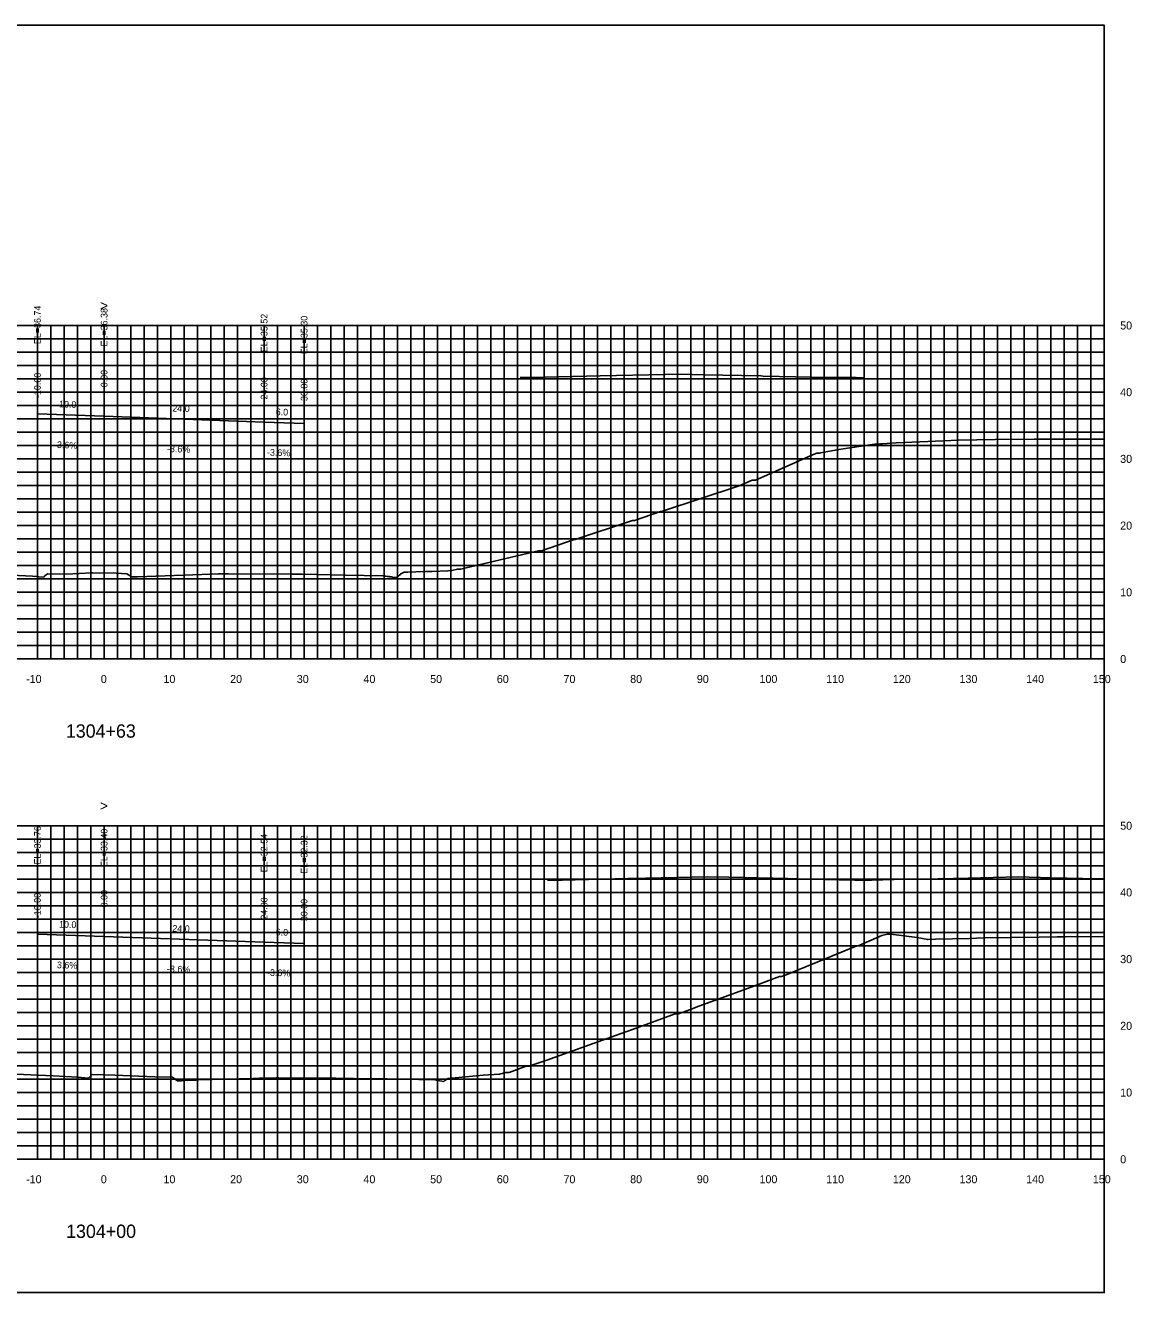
# Model space of a CAD drawing. Extents: x 1797714 to 1804825, y 249015 to 250269.
# Drawn here: x 1803612.3 to 1803778.3, y 249628.2 to 249818.2 of the extents above; entities that cross this region are included whole.
import ezdxf

# ---------------------------------------------------------------- set-up
doc = ezdxf.new("R2010")
doc.units = 0
for name, color, linetype in [('1', 7, 'Continuous'), ('10', 7, 'Continuous'), ('3', 7, 'Continuous'), ('31', 7, 'Continuous'), ('4', 7, 'Continuous'), ('60', 7, 'Continuous'), ('CL-CNST', 7, 'Continuous'), ('Level 62', 7, 'Continuous'), ('M-ROADS', 7, 'Continuous')]:
    doc.layers.add(name, color=color, linetype=linetype)

msp = doc.modelspace()

# ---------------------------------------------------------------- linework, layer by layer
for p, q in [((1803614.16, 249759.91), (1803614.16, 249761.91)), ((1803624.16, 249759.55), (1803624.16, 249761.55)), ((1803648.16, 249758.69), (1803648.16, 249760.69)), ((1803654.16, 249758.47), (1803654.16, 249760.47)), ((1803614.16, 249681.93), (1803614.16, 249683.93)), ((1803624.16, 249681.57), (1803624.16, 249683.57)), ((1803648.16, 249680.71), (1803648.16, 249682.71)), ((1803654.16, 249680.49), (1803654.16, 249682.49))]:
    msp.add_line(p, q)
msp.add_lwpolyline([(1803474.16, 249628.17), (1803774.16, 249628.17), (1803774.16, 249818.17), (1803474.16, 249818.17)], close=True)
at = {"layer": '60'}
for p, q in [((1803774.16, 249723.17), (1803774.16, 249773.17)), ((1803774.22, 249773.17), (1803774.16, 249773.17)), ((1803774.22, 249763.17), (1803774.16, 249763.17)), ((1803774.22, 249753.17), (1803774.16, 249753.17)), ((1803774.22, 249743.17), (1803774.16, 249743.17)), ((1803774.22, 249733.17), (1803774.16, 249733.17)), ((1803474.16, 249723.17), (1803774.16, 249723.17)), ((1803614.16, 249723.11), (1803614.16, 249723.17)), ((1803624.16, 249723.11), (1803624.16, 249723.17)), ((1803634.16, 249723.11), (1803634.16, 249723.17)), ((1803644.16, 249723.11), (1803644.16, 249723.17)), ((1803654.16, 249723.11), (1803654.16, 249723.17)), ((1803664.16, 249723.11), (1803664.16, 249723.17)), ((1803674.16, 249723.11), (1803674.16, 249723.17)), ((1803684.16, 249723.11), (1803684.16, 249723.17)), ((1803694.16, 249723.11), (1803694.16, 249723.17)), ((1803704.16, 249723.11), (1803704.16, 249723.17)), ((1803714.16, 249723.11), (1803714.16, 249723.17)), ((1803724.16, 249723.11), (1803724.16, 249723.17)), ((1803734.16, 249723.11), (1803734.16, 249723.17)), ((1803744.16, 249723.11), (1803744.16, 249723.17)), ((1803754.16, 249723.11), (1803754.16, 249723.17)), ((1803764.16, 249723.11), (1803764.16, 249723.17)), ((1803774.16, 249723.11), (1803774.16, 249723.17)), ((1803774.22, 249723.17), (1803774.16, 249723.17)), ((1803774.16, 249648.17), (1803774.16, 249698.17)), ((1803774.22, 249698.17), (1803774.16, 249698.17)), ((1803774.22, 249688.17), (1803774.16, 249688.17)), ((1803774.22, 249678.17), (1803774.16, 249678.17)), ((1803774.22, 249668.17), (1803774.16, 249668.17)), ((1803774.22, 249658.17), (1803774.16, 249658.17)), ((1803474.16, 249648.17), (1803774.16, 249648.17)), ((1803614.16, 249648.11), (1803614.16, 249648.17)), ((1803624.16, 249648.11), (1803624.16, 249648.17)), ((1803634.16, 249648.11), (1803634.16, 249648.17)), ((1803644.16, 249648.11), (1803644.16, 249648.17)), ((1803654.16, 249648.11), (1803654.16, 249648.17)), ((1803664.16, 249648.11), (1803664.16, 249648.17)), ((1803674.16, 249648.11), (1803674.16, 249648.17)), ((1803684.16, 249648.11), (1803684.16, 249648.17)), ((1803694.16, 249648.11), (1803694.16, 249648.17)), ((1803704.16, 249648.11), (1803704.16, 249648.17)), ((1803714.16, 249648.11), (1803714.16, 249648.17)), ((1803724.16, 249648.11), (1803724.16, 249648.17)), ((1803734.16, 249648.11), (1803734.16, 249648.17)), ((1803744.16, 249648.11), (1803744.16, 249648.17)), ((1803754.16, 249648.11), (1803754.16, 249648.17)), ((1803764.16, 249648.11), (1803764.16, 249648.17)), ((1803774.16, 249648.11), (1803774.16, 249648.17)), ((1803774.22, 249648.17), (1803774.16, 249648.17))]:
    msp.add_line(p, q, dxfattribs=at)
at = {"layer": 'CL-CNST'}
for points in [[(1803686.54, 249765.35), (1803688.22, 249765.39), (1803698.58, 249765.61), (1803708.3, 249765.82), (1803710.63, 249765.87), (1803714.11, 249765.79), (1803722.67, 249765.6), (1803723, 249765.59), (1803732.7, 249765.37), (1803732.79, 249765.37), (1803733.95, 249765.35), (1803733.95, 249765.35), (1803734.04, 249765.35), (1803734.82, 249765.36), (1803735.82, 249765.39), (1803736.94, 249765.37), (1803738.17, 249765.34)], [(1803614.16, 249759.91), (1803624.16, 249759.55), (1803648.16, 249758.69), (1803654.16, 249758.47)], [(1803690.67, 249689.99), (1803692.88, 249690.03), (1803702.69, 249690.25), (1803705.37, 249690.3), (1803714.71, 249690.51), (1803717.86, 249690.44), (1803726.72, 249690.24), (1803729.72, 249690.17), (1803736.74, 249690.02), (1803737.14, 249690.01), (1803737.98, 249689.99), (1803737.99, 249689.99), (1803737.99, 249689.99), (1803738.4, 249690), (1803739.24, 249690.01), (1803742.64, 249690.09), (1803749.25, 249690.23), (1803753.75, 249690.33), (1803761.27, 249690.49), (1803766.24, 249690.38), (1803773.29, 249690.22), (1803774.16, 249690.2)], [(1803614.16, 249681.93), (1803624.16, 249681.57), (1803648.16, 249680.71), (1803654.16, 249680.49)]]:
    msp.add_lwpolyline(points, dxfattribs=at)
at = {"layer": 'Level 62'}
for p, q in [((1803474.16, 249773.17), (1803774.16, 249773.17)), ((1803614.16, 249723.17), (1803614.16, 249773.17)), ((1803616.16, 249723.17), (1803616.16, 249773.17)), ((1803618.16, 249723.17), (1803618.16, 249773.17)), ((1803620.16, 249723.17), (1803620.16, 249773.17)), ((1803622.16, 249723.17), (1803622.16, 249773.17)), ((1803624.16, 249723.17), (1803624.16, 249773.17)), ((1803626.16, 249723.17), (1803626.16, 249773.17)), ((1803628.16, 249723.17), (1803628.16, 249773.17)), ((1803630.16, 249723.17), (1803630.16, 249773.17)), ((1803632.16, 249723.17), (1803632.16, 249773.17)), ((1803634.16, 249723.17), (1803634.16, 249773.17)), ((1803636.16, 249723.17), (1803636.16, 249773.17)), ((1803638.16, 249723.17), (1803638.16, 249773.17)), ((1803640.16, 249723.17), (1803640.16, 249773.17)), ((1803642.16, 249723.17), (1803642.16, 249773.17)), ((1803644.16, 249723.17), (1803644.16, 249773.17)), ((1803646.16, 249723.17), (1803646.16, 249773.17)), ((1803648.16, 249723.17), (1803648.16, 249773.17)), ((1803650.16, 249723.17), (1803650.16, 249773.17)), ((1803652.16, 249723.17), (1803652.16, 249773.17)), ((1803654.16, 249723.17), (1803654.16, 249773.17)), ((1803656.16, 249723.17), (1803656.16, 249773.17)), ((1803658.16, 249723.17), (1803658.16, 249773.17)), ((1803660.16, 249723.17), (1803660.16, 249773.17)), ((1803662.16, 249723.17), (1803662.16, 249773.17)), ((1803664.16, 249723.17), (1803664.16, 249773.17)), ((1803666.16, 249723.17), (1803666.16, 249773.17)), ((1803668.16, 249723.17), (1803668.16, 249773.17)), ((1803670.16, 249723.17), (1803670.16, 249773.17)), ((1803672.16, 249723.17), (1803672.16, 249773.17)), ((1803674.16, 249723.17), (1803674.16, 249773.17)), ((1803676.16, 249723.17), (1803676.16, 249773.17)), ((1803678.16, 249723.17), (1803678.16, 249773.17)), ((1803680.16, 249723.17), (1803680.16, 249773.17)), ((1803682.16, 249723.17), (1803682.16, 249773.17)), ((1803684.16, 249723.17), (1803684.16, 249773.17)), ((1803686.16, 249723.17), (1803686.16, 249773.17)), ((1803688.16, 249723.17), (1803688.16, 249773.17)), ((1803690.16, 249723.17), (1803690.16, 249773.17)), ((1803692.16, 249723.17), (1803692.16, 249773.17)), ((1803694.16, 249723.17), (1803694.16, 249773.17)), ((1803696.16, 249723.17), (1803696.16, 249773.17)), ((1803698.16, 249723.17), (1803698.16, 249773.17)), ((1803700.16, 249723.17), (1803700.16, 249773.17)), ((1803702.16, 249723.17), (1803702.16, 249773.17)), ((1803704.16, 249723.17), (1803704.16, 249773.17)), ((1803706.16, 249723.17), (1803706.16, 249773.17)), ((1803708.16, 249723.17), (1803708.16, 249773.17)), ((1803710.16, 249723.17), (1803710.16, 249773.17)), ((1803712.16, 249723.17), (1803712.16, 249773.17)), ((1803714.16, 249723.17), (1803714.16, 249773.17)), ((1803716.16, 249723.17), (1803716.16, 249773.17)), ((1803718.16, 249723.17), (1803718.16, 249773.17)), ((1803720.16, 249723.17), (1803720.16, 249773.17)), ((1803722.16, 249723.17), (1803722.16, 249773.17)), ((1803724.16, 249723.17), (1803724.16, 249773.17)), ((1803726.16, 249723.17), (1803726.16, 249773.17)), ((1803728.16, 249723.17), (1803728.16, 249773.17)), ((1803730.16, 249723.17), (1803730.16, 249773.17)), ((1803732.16, 249723.17), (1803732.16, 249773.17)), ((1803734.16, 249723.17), (1803734.16, 249773.17)), ((1803736.16, 249723.17), (1803736.16, 249773.17)), ((1803738.16, 249723.17), (1803738.16, 249773.17)), ((1803740.16, 249723.17), (1803740.16, 249773.17)), ((1803742.16, 249723.17), (1803742.16, 249773.17)), ((1803744.16, 249723.17), (1803744.16, 249773.17)), ((1803746.16, 249723.17), (1803746.16, 249773.17)), ((1803748.16, 249723.17), (1803748.16, 249773.17)), ((1803750.16, 249723.17), (1803750.16, 249773.17)), ((1803752.16, 249723.17), (1803752.16, 249773.17)), ((1803754.16, 249723.17), (1803754.16, 249773.17)), ((1803756.16, 249723.17), (1803756.16, 249773.17)), ((1803758.16, 249723.17), (1803758.16, 249773.17)), ((1803760.16, 249723.17), (1803760.16, 249773.17)), ((1803762.16, 249723.17), (1803762.16, 249773.17)), ((1803764.16, 249723.17), (1803764.16, 249773.17)), ((1803766.16, 249723.17), (1803766.16, 249773.17)), ((1803768.16, 249723.17), (1803768.16, 249773.17)), ((1803770.16, 249723.17), (1803770.16, 249773.17)), ((1803772.16, 249723.17), (1803772.16, 249773.17)), ((1803774.16, 249723.17), (1803774.16, 249773.17)), ((1803474.16, 249771.17), (1803774.16, 249771.17)), ((1803474.16, 249769.17), (1803774.16, 249769.17)), ((1803474.16, 249767.17), (1803774.16, 249767.17)), ((1803474.16, 249765.17), (1803774.16, 249765.17)), ((1803474.16, 249763.17), (1803774.16, 249763.17)), ((1803474.16, 249761.17), (1803774.16, 249761.17)), ((1803474.16, 249759.17), (1803774.16, 249759.17)), ((1803474.16, 249757.17), (1803774.16, 249757.17)), ((1803474.16, 249755.17), (1803774.16, 249755.17)), ((1803474.16, 249753.17), (1803774.16, 249753.17)), ((1803474.16, 249751.17), (1803774.16, 249751.17)), ((1803474.16, 249749.17), (1803774.16, 249749.17)), ((1803474.16, 249747.17), (1803774.16, 249747.17)), ((1803474.16, 249745.17), (1803774.16, 249745.17)), ((1803474.16, 249743.17), (1803774.16, 249743.17)), ((1803474.16, 249741.17), (1803774.16, 249741.17)), ((1803474.16, 249739.17), (1803774.16, 249739.17)), ((1803474.16, 249737.17), (1803774.16, 249737.17)), ((1803474.16, 249735.17), (1803774.16, 249735.17)), ((1803474.16, 249733.17), (1803774.16, 249733.17)), ((1803474.16, 249731.17), (1803774.16, 249731.17)), ((1803474.16, 249729.17), (1803774.16, 249729.17)), ((1803474.16, 249727.17), (1803774.16, 249727.17)), ((1803474.16, 249725.17), (1803774.16, 249725.17)), ((1803474.16, 249723.17), (1803774.16, 249723.17)), ((1803474.16, 249698.17), (1803774.16, 249698.17)), ((1803614.16, 249648.17), (1803614.16, 249698.17)), ((1803616.16, 249648.17), (1803616.16, 249698.17)), ((1803618.16, 249648.17), (1803618.16, 249698.17)), ((1803620.16, 249648.17), (1803620.16, 249698.17)), ((1803622.16, 249648.17), (1803622.16, 249698.17)), ((1803624.16, 249648.17), (1803624.16, 249698.17)), ((1803626.16, 249648.17), (1803626.16, 249698.17)), ((1803628.16, 249648.17), (1803628.16, 249698.17)), ((1803630.16, 249648.17), (1803630.16, 249698.17)), ((1803632.16, 249648.17), (1803632.16, 249698.17)), ((1803634.16, 249648.17), (1803634.16, 249698.17)), ((1803636.16, 249648.17), (1803636.16, 249698.17)), ((1803638.16, 249648.17), (1803638.16, 249698.17)), ((1803640.16, 249648.17), (1803640.16, 249698.17)), ((1803642.16, 249648.17), (1803642.16, 249698.17)), ((1803644.16, 249648.17), (1803644.16, 249698.17)), ((1803646.16, 249648.17), (1803646.16, 249698.17)), ((1803648.16, 249648.17), (1803648.16, 249698.17)), ((1803650.16, 249648.17), (1803650.16, 249698.17)), ((1803652.16, 249648.17), (1803652.16, 249698.17)), ((1803654.16, 249648.17), (1803654.16, 249698.17)), ((1803656.16, 249648.17), (1803656.16, 249698.17)), ((1803658.16, 249648.17), (1803658.16, 249698.17)), ((1803660.16, 249648.17), (1803660.16, 249698.17)), ((1803662.16, 249648.17), (1803662.16, 249698.17)), ((1803664.16, 249648.17), (1803664.16, 249698.17)), ((1803666.16, 249648.17), (1803666.16, 249698.17)), ((1803668.16, 249648.17), (1803668.16, 249698.17)), ((1803670.16, 249648.17), (1803670.16, 249698.17)), ((1803672.16, 249648.17), (1803672.16, 249698.17)), ((1803674.16, 249648.17), (1803674.16, 249698.17)), ((1803676.16, 249648.17), (1803676.16, 249698.17)), ((1803678.16, 249648.17), (1803678.16, 249698.17)), ((1803680.16, 249648.17), (1803680.16, 249698.17)), ((1803682.16, 249648.17), (1803682.16, 249698.17)), ((1803684.16, 249648.17), (1803684.16, 249698.17)), ((1803686.16, 249648.17), (1803686.16, 249698.17)), ((1803688.16, 249648.17), (1803688.16, 249698.17)), ((1803690.16, 249648.17), (1803690.16, 249698.17)), ((1803692.16, 249648.17), (1803692.16, 249698.17)), ((1803694.16, 249648.17), (1803694.16, 249698.17)), ((1803696.16, 249648.17), (1803696.16, 249698.17)), ((1803698.16, 249648.17), (1803698.16, 249698.17)), ((1803700.16, 249648.17), (1803700.16, 249698.17)), ((1803702.16, 249648.17), (1803702.16, 249698.17)), ((1803704.16, 249648.17), (1803704.16, 249698.17)), ((1803706.16, 249648.17), (1803706.16, 249698.17)), ((1803708.16, 249648.17), (1803708.16, 249698.17)), ((1803710.16, 249648.17), (1803710.16, 249698.17)), ((1803712.16, 249648.17), (1803712.16, 249698.17)), ((1803714.16, 249648.17), (1803714.16, 249698.17)), ((1803716.16, 249648.17), (1803716.16, 249698.17)), ((1803718.16, 249648.17), (1803718.16, 249698.17)), ((1803720.16, 249648.17), (1803720.16, 249698.17)), ((1803722.16, 249648.17), (1803722.16, 249698.17)), ((1803724.16, 249648.17), (1803724.16, 249698.17)), ((1803726.16, 249648.17), (1803726.16, 249698.17)), ((1803728.16, 249648.17), (1803728.16, 249698.17)), ((1803730.16, 249648.17), (1803730.16, 249698.17)), ((1803732.16, 249648.17), (1803732.16, 249698.17)), ((1803734.16, 249648.17), (1803734.16, 249698.17)), ((1803736.16, 249648.17), (1803736.16, 249698.17)), ((1803738.16, 249648.17), (1803738.16, 249698.17)), ((1803740.16, 249648.17), (1803740.16, 249698.17)), ((1803742.16, 249648.17), (1803742.16, 249698.17)), ((1803744.16, 249648.17), (1803744.16, 249698.17)), ((1803746.16, 249648.17), (1803746.16, 249698.17)), ((1803748.16, 249648.17), (1803748.16, 249698.17)), ((1803750.16, 249648.17), (1803750.16, 249698.17)), ((1803752.16, 249648.17), (1803752.16, 249698.17)), ((1803754.16, 249648.17), (1803754.16, 249698.17)), ((1803756.16, 249648.17), (1803756.16, 249698.17)), ((1803758.16, 249648.17), (1803758.16, 249698.17)), ((1803760.16, 249648.17), (1803760.16, 249698.17)), ((1803762.16, 249648.17), (1803762.16, 249698.17)), ((1803764.16, 249648.17), (1803764.16, 249698.17)), ((1803766.16, 249648.17), (1803766.16, 249698.17)), ((1803768.16, 249648.17), (1803768.16, 249698.17)), ((1803770.16, 249648.17), (1803770.16, 249698.17)), ((1803772.16, 249648.17), (1803772.16, 249698.17)), ((1803774.16, 249648.17), (1803774.16, 249698.17)), ((1803474.16, 249696.17), (1803774.16, 249696.17)), ((1803474.16, 249694.17), (1803774.16, 249694.17)), ((1803474.16, 249692.17), (1803774.16, 249692.17)), ((1803474.16, 249690.17), (1803774.16, 249690.17)), ((1803474.16, 249688.17), (1803774.16, 249688.17)), ((1803474.16, 249686.17), (1803774.16, 249686.17)), ((1803474.16, 249684.17), (1803774.16, 249684.17)), ((1803474.16, 249682.17), (1803774.16, 249682.17)), ((1803474.16, 249680.17), (1803774.16, 249680.17)), ((1803474.16, 249678.17), (1803774.16, 249678.17)), ((1803474.16, 249676.17), (1803774.16, 249676.17)), ((1803474.16, 249674.17), (1803774.16, 249674.17)), ((1803474.16, 249672.17), (1803774.16, 249672.17)), ((1803474.16, 249670.17), (1803774.16, 249670.17)), ((1803474.16, 249668.17), (1803774.16, 249668.17)), ((1803474.16, 249666.17), (1803774.16, 249666.17)), ((1803474.16, 249664.17), (1803774.16, 249664.17)), ((1803474.16, 249662.17), (1803774.16, 249662.17)), ((1803474.16, 249660.17), (1803774.16, 249660.17)), ((1803474.16, 249658.17), (1803774.16, 249658.17)), ((1803474.16, 249656.17), (1803774.16, 249656.17)), ((1803474.16, 249654.17), (1803774.16, 249654.17)), ((1803474.16, 249652.17), (1803774.16, 249652.17)), ((1803474.16, 249650.17), (1803774.16, 249650.17)), ((1803474.16, 249648.17), (1803774.16, 249648.17))]:
    msp.add_line(p, q, dxfattribs=at)
at = {"layer": 'M-ROADS'}
for points in [[(1803603.97, 249736.05), (1803613.43, 249735.6), (1803614.05, 249735.53), (1803614.39, 249735.51), (1803615.1, 249735.44), (1803615.29, 249735.62), (1803615.65, 249735.94), (1803618.58, 249735.88), (1803622.26, 249736.07), (1803622.46, 249736.07), (1803625.97, 249736.02), (1803627.59, 249735.96), (1803627.83, 249735.79), (1803628.26, 249735.47), (1803629.06, 249735.48), (1803629.09, 249735.48), (1803629.13, 249735.48), (1803629.16, 249735.48), (1803640.24, 249735.88), (1803641.31, 249735.92), (1803641.78, 249735.92), (1803642.71, 249735.92), (1803642.83, 249735.92), (1803652.37, 249735.89), (1803653.86, 249735.88), (1803660.37, 249735.76), (1803665.95, 249735.65), (1803666.13, 249735.63), (1803666.23, 249735.61), (1803666.41, 249735.59), (1803666.63, 249735.56), (1803666.79, 249735.54), (1803666.92, 249735.52), (1803667.03, 249735.51), (1803667.11, 249735.49), (1803667.18, 249735.49), (1803667.25, 249735.48), (1803667.3, 249735.47), (1803667.35, 249735.46), (1803667.39, 249735.46), (1803667.42, 249735.45), (1803667.46, 249735.45), (1803668.02, 249735.39), (1803668.51, 249735.8), (1803668.59, 249735.86), (1803668.66, 249735.95), (1803669.18, 249736.17), (1803669.2, 249736.17), (1803669.2, 249736.17), (1803669.67, 249736.17), (1803669.7, 249736.17), (1803670.89, 249736.22), (1803672.34, 249736.27), (1803673.35, 249736.31), (1803675.71, 249736.39), (1803676.21, 249736.45), (1803676.32, 249736.46), (1803677.16, 249736.65), (1803677.66, 249736.65), (1803678.45, 249736.81), (1803689.33, 249739.4), (1803689.55, 249739.39), (1803689.77, 249739.38), (1803694.65, 249741.07), (1803694.83, 249741.07), (1803703.4, 249743.92), (1803703.69, 249743.91), (1803707.61, 249745.29), (1803707.77, 249745.29), (1803719.39, 249749.12), (1803721.34, 249749.97), (1803721.65, 249749.98), (1803721.88, 249749.99), (1803730.64, 249753.89), (1803731.04, 249754.05), (1803731.22, 249754.05), (1803731.35, 249754.05), (1803731.56, 249754.05), (1803731.59, 249754.07), (1803734.37, 249754.58), (1803735.01, 249754.68), (1803739.73, 249755.36), (1803740.6, 249755.42), (1803740.92, 249755.42), (1803742.96, 249755.58), (1803750.08, 249755.9), (1803752.32, 249756), (1803757.8, 249756.06), (1803763.67, 249756.12), (1803770.27, 249756.11), (1803774.16, 249756.11)], [(1803607.58, 249661.07), (1803616.53, 249660.68), (1803620.2, 249660.47), (1803620.73, 249660.42), (1803621.83, 249660.34), (1803621.98, 249660.49), (1803622.37, 249660.86), (1803625.75, 249660.75), (1803631.79, 249660.54), (1803634.44, 249660.45), (1803635.01, 249660.02), (1803635.18, 249659.9), (1803635.34, 249659.91), (1803635.49, 249659.92), (1803635.76, 249659.94), (1803636.78, 249660.01), (1803637.99, 249660.04), (1803638.31, 249660.05), (1803644.47, 249660.22), (1803646.47, 249660.28), (1803647.46, 249660.31), (1803647.62, 249660.31), (1803648.06, 249660.32), (1803649.89, 249660.36), (1803649.94, 249660.36), (1803650.37, 249660.35), (1803653.5, 249660.34), (1803653.75, 249660.34), (1803655.05, 249660.33), (1803658.4, 249660.31), (1803658.89, 249660.31), (1803661.66, 249660.29), (1803665.96, 249660.21), (1803666.61, 249660.2), (1803673.74, 249660.06), (1803674.16, 249659.98), (1803675.09, 249659.82), (1803675.24, 249659.96), (1803675.75, 249660.27), (1803681, 249660.79), (1803683.45, 249660.92), (1803684.41, 249661.15), (1803684.65, 249661.15), (1803684.91, 249661.15), (1803687.48, 249662.11), (1803687.9, 249662.13), (1803688.02, 249662.17), (1803690.11, 249662.86), (1803690.54, 249663), (1803700.88, 249666.74), (1803703.41, 249667.64), (1803709.25, 249669.75), (1803709.8, 249669.96), (1803709.82, 249669.96), (1803710.3, 249669.97), (1803711.96, 249670.57), (1803712.12, 249670.63), (1803712.96, 249670.96), (1803721.62, 249674.11), (1803725.48, 249675.58), (1803725.75, 249675.56), (1803725.92, 249675.62), (1803726.21, 249675.72), (1803737.04, 249680.14), (1803737.27, 249680.15), (1803740.83, 249681.72), (1803741.65, 249681.9), (1803741.91, 249681.9), (1803742.17, 249681.9), (1803746.13, 249681.42), (1803747.7, 249681.11), (1803748.84, 249681.14), (1803753.98, 249681.28), (1803756.07, 249681.34), (1803764.42, 249681.45), (1803767.12, 249681.49), (1803768.34, 249681.5), (1803774.16, 249681.56)]]:
    msp.add_lwpolyline(points, dxfattribs=at)

# ---------------------------------------------------------------- texts
at = {"layer": '1'}
for s, p in [('1304+63', (1803618.42, 249711.37)), ('1304+00', (1803618.46, 249636.37))]:
    msp.add_text(s, height=2, dxfattribs=at).set_placement(p)
at = {"layer": '10'}
for s, p in [('-10', (1803612.46, 249719.57)), ('0', (1803623.66, 249719.57)), ('10', (1803633.06, 249719.57)), ('20', (1803643.06, 249719.57)), ('30', (1803653.06, 249719.57)), ('40', (1803663.06, 249719.57)), ('50', (1803673.06, 249719.57)), ('60', (1803683.06, 249719.57)), ('70', (1803693.06, 249719.57)), ('80', (1803703.06, 249719.57)), ('90', (1803713.06, 249719.57)), ('100', (1803722.46, 249719.57)), ('110', (1803732.46, 249719.57)), ('120', (1803742.46, 249719.57)), ('130', (1803752.46, 249719.57)), ('140', (1803762.46, 249719.57)), ('150', (1803772.46, 249719.57)), ('-10', (1803612.46, 249644.57)), ('0', (1803623.66, 249644.57)), ('10', (1803633.06, 249644.57)), ('20', (1803643.06, 249644.57)), ('30', (1803653.06, 249644.57)), ('40', (1803663.06, 249644.57)), ('50', (1803673.06, 249644.57)), ('60', (1803683.06, 249644.57)), ('70', (1803693.06, 249644.57)), ('80', (1803703.06, 249644.57)), ('90', (1803713.06, 249644.57)), ('100', (1803722.46, 249644.57)), ('110', (1803732.46, 249644.57)), ('120', (1803742.46, 249644.57)), ('130', (1803752.46, 249644.57)), ('140', (1803762.46, 249644.57)), ('150', (1803772.46, 249644.57))]:
    msp.add_text(s, height=1.2, dxfattribs=at).set_placement(p)
at = {"layer": '3'}
for s, p in [('EL=36.74', (1803614.66, 249770.38)), ('EL=36.38', (1803624.66, 249770.02)), ('EL=35.52', (1803648.66, 249769.16)), ('EL=35.30', (1803654.66, 249768.86)), ('0.00', (1803624.66, 249763.91)), ('-10.00', (1803614.66, 249762.29)), ('24.00', (1803648.66, 249762.06)), ('30.00', (1803654.66, 249761.84)), ('EL=33.76', (1803614.66, 249692.35)), ('EL=33.40', (1803624.66, 249691.96)), ('EL=32.54', (1803648.66, 249691.18)), ('EL=32.32', (1803654.66, 249690.96)), ('-10.00', (1803614.66, 249684.31)), ('0.00', (1803624.66, 249685.93)), ('24.00', (1803648.66, 249684.08)), ('30.00', (1803654.66, 249683.86))]:
    msp.add_text(s, height=1, rotation=90, dxfattribs=at).set_placement(p)
at = {"layer": '31'}
for s, p in [('50', (1803776.56, 249772.57)), ('40', (1803776.56, 249762.57)), ('30', (1803776.56, 249752.57)), ('20', (1803776.56, 249742.57)), ('10', (1803776.56, 249732.57)), ('0', (1803776.56, 249722.57)), ('50', (1803776.56, 249697.57)), ('40', (1803776.56, 249687.57)), ('30', (1803776.56, 249677.57)), ('20', (1803776.56, 249667.57)), ('10', (1803776.56, 249657.57)), ('0', (1803776.56, 249647.57))]:
    msp.add_text(s, height=1.2, dxfattribs=at).set_placement(p)
at = {"layer": '4'}
for s, p in [('10.0', (1803617.38, 249760.9)), ('24.0', (1803634.38, 249760.28)), ('6.0', (1803649.88, 249759.73)), ('3.6%', (1803617.07, 249754.8)), ('-3.6%', (1803633.57, 249754.21)), ('-3.6%', (1803648.57, 249753.67)), ('10.0', (1803617.38, 249682.91)), ('24.0', (1803634.38, 249682.3)), ('6.0', (1803649.88, 249681.74)), ('3.6%', (1803617.07, 249676.82)), ('-3.6%', (1803633.57, 249676.23)), ('-3.6%', (1803648.57, 249675.69))]:
    msp.add_text(s, height=1, rotation=357.9382, dxfattribs=at).set_placement(p)
at = {"layer": '60'}
for p in [(1803623.55, 249775.42), (1803623.55, 249700.42)]:
    msp.add_text('>', height=1.5, dxfattribs=at).set_placement(p)

doc.saveas('drawing.dxf')
